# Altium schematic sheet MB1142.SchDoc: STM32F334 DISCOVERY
size A4; CompanyName: STM; DocumentNumber: MB1142; Revision: B-02; SheetNumber: 1; SheetTotal: 5; PageSetup: Record=PageOptions|CenterHorizontal=True|CenterVertical=True|PrintScale=-0.03|XCorrection=1.00|YCorrection=1.00|PrintKind=0|BorderSize=5000000|LeftOffset=0|BottomOffset=0|Orientation=2|PaperLength=1000|PaperWidth=1000|Scale=100|PaperSource=15|PrintQuality=1200|MediaType=1|DitherType=10|PaperKind=A4|PrintScaleMode=1; Project: STM32F3348-DISCO
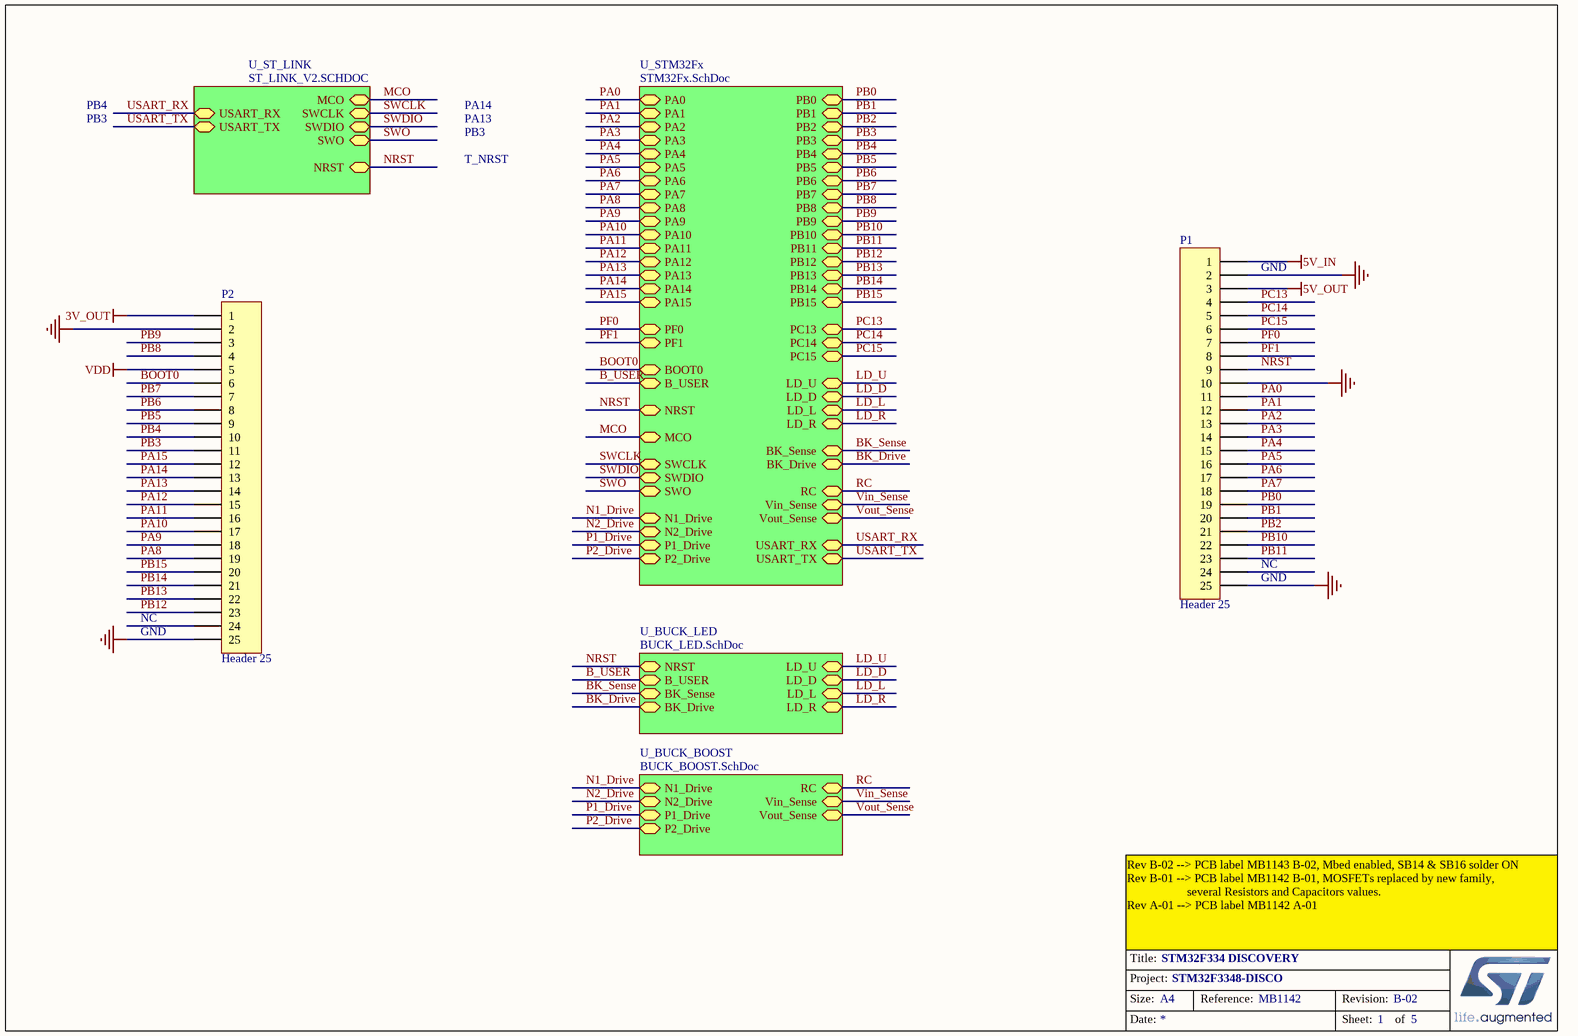
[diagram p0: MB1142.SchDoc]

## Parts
P1  Header 25  [HDR1X25]
P2  Header 25  [HDR1X25]

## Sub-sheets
U_BUCK_BOOST = BUCK_BOOST.SchDoc: N1_Drive, N2_Drive, Vout_Sense, P1_Drive, P2_Drive, Vin_Sense, RC
U_BUCK_LED = BUCK_LED.SchDoc: NRST, B_USER, BK_Sense, BK_Drive, LD_D, LD_U, LD_L, LD_R
U_ST_LINK = ST_LINK_V2.SCHDOC: NRST, MCO, SWDIO, SWCLK, SWO, USART_RX, USART_TX
U_STM32Fx = STM32Fx.SchDoc: PB8, BOOT0, NRST, PC15, PC14, PF1, PF0, MCO, PC13, PA0, PA1, PA2, PA3, PA4, PA5, PA6, PA7, PA8, PA9, PA10, PA11, PA12, PA13, PA14, PA15, PB0, PB1, PB2, PB3, PB4, PB5, PB6, PB7, PB9, PB10, PB11, PB12, PB13, PB14, PB15, B_USER, LD_D, LD_U, LD_L, LD_R, RC, Vout_Sense, P2_Drive, BK_Sense, Vin_Sense, BK_Drive, N1_Drive, P1_Drive, N2_Drive, SWCLK, SWDIO, SWO, USART_TX, USART_RX

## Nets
3V_OUT: P2.1
5V_IN: P1.1
5V_OUT: P1.3
GND: P1.2 P1.10 P1.25 P2.2 P2.25
VDD: P2.5
B_USER: sheet U_STM32Fx/B_USER, sheet U_BUCK_LED/B_USER
BK_Drive: sheet U_STM32Fx/BK_Drive, sheet U_BUCK_LED/BK_Drive
BK_Sense: sheet U_STM32Fx/BK_Sense, sheet U_BUCK_LED/BK_Sense
BOOT0: P2.6 ; sheet U_STM32Fx/BOOT0
LD_D: sheet U_STM32Fx/LD_D, sheet U_BUCK_LED/LD_D
LD_L: sheet U_STM32Fx/LD_L, sheet U_BUCK_LED/LD_L
LD_R: sheet U_STM32Fx/LD_R, sheet U_BUCK_LED/LD_R
LD_U: sheet U_STM32Fx/LD_U, sheet U_BUCK_LED/LD_U
MCO: sheet U_ST_LINK/MCO, sheet U_STM32Fx/MCO
N1_Drive: sheet U_STM32Fx/N1_Drive, sheet U_BUCK_BOOST/N1_Drive
N2_Drive: sheet U_STM32Fx/N2_Drive, sheet U_BUCK_BOOST/N2_Drive
NRST: P1.9 ; sheet U_ST_LINK/NRST, sheet U_STM32Fx/NRST, sheet U_BUCK_LED/NRST
P1_Drive: sheet U_STM32Fx/P1_Drive, sheet U_BUCK_BOOST/P1_Drive
P2_Drive: sheet U_STM32Fx/P2_Drive, sheet U_BUCK_BOOST/P2_Drive
PA0: P1.11 ; sheet U_STM32Fx/PA0
PA1: P1.12 ; sheet U_STM32Fx/PA1
PA2: P1.13 ; sheet U_STM32Fx/PA2
PA3: P1.14 ; sheet U_STM32Fx/PA3
PA4: P1.15 ; sheet U_STM32Fx/PA4
PA5: P1.16 ; sheet U_STM32Fx/PA5
PA6: P1.17 ; sheet U_STM32Fx/PA6
PA7: P1.18 ; sheet U_STM32Fx/PA7
PA8: P2.19 ; sheet U_STM32Fx/PA8
PA9: P2.18 ; sheet U_STM32Fx/PA9
PA10: P2.17 ; sheet U_STM32Fx/PA10
PA11: P2.16 ; sheet U_STM32Fx/PA11
PA12: P2.15 ; sheet U_STM32Fx/PA12
PA13: P2.14 ; sheet U_STM32Fx/PA13
PA14: P2.13 ; sheet U_STM32Fx/PA14
PA15: P2.12 ; sheet U_STM32Fx/PA15
PB0: P1.19 ; sheet U_STM32Fx/PB0
PB1: P1.20 ; sheet U_STM32Fx/PB1
PB2: P1.21 ; sheet U_STM32Fx/PB2
PB3: P2.11 ; sheet U_STM32Fx/PB3
PB4: P2.10 ; sheet U_STM32Fx/PB4
PB5: P2.9 ; sheet U_STM32Fx/PB5
PB6: P2.8 ; sheet U_STM32Fx/PB6
PB7: P2.7 ; sheet U_STM32Fx/PB7
PB8: P2.4 ; sheet U_STM32Fx/PB8
PB9: P2.3 ; sheet U_STM32Fx/PB9
PB10: P1.22 ; sheet U_STM32Fx/PB10
PB11: P1.23 ; sheet U_STM32Fx/PB11
PB12: P2.23 ; sheet U_STM32Fx/PB12
PB13: P2.22 ; sheet U_STM32Fx/PB13
PB14: P2.21 ; sheet U_STM32Fx/PB14
PB15: P2.20 ; sheet U_STM32Fx/PB15
PC13: P1.4 ; sheet U_STM32Fx/PC13
PC14: P1.5 ; sheet U_STM32Fx/PC14
PC15: P1.6 ; sheet U_STM32Fx/PC15
PF0: P1.7 ; sheet U_STM32Fx/PF0
PF1: P1.8 ; sheet U_STM32Fx/PF1
RC: sheet U_STM32Fx/RC, sheet U_BUCK_BOOST/RC
SWCLK: sheet U_ST_LINK/SWCLK, sheet U_STM32Fx/SWCLK
SWDIO: sheet U_ST_LINK/SWDIO, sheet U_STM32Fx/SWDIO
SWO: sheet U_ST_LINK/SWO, sheet U_STM32Fx/SWO
USART_RX: sheet U_ST_LINK/USART_RX, sheet U_STM32Fx/USART_RX
USART_TX: sheet U_ST_LINK/USART_TX, sheet U_STM32Fx/USART_TX
Vin_Sense: sheet U_STM32Fx/Vin_Sense, sheet U_BUCK_BOOST/Vin_Sense
Vout_Sense: sheet U_STM32Fx/Vout_Sense, sheet U_BUCK_BOOST/Vout_Sense

Not connected (* = marked no-connect by the designer): P1 24; P2 24

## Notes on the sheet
- PB4
- PA14
- PB3
- PA13
- T_NRST
- (near P1) GND
- (near P1) NC
- GND
- NC
- Rev B-02 --> PCB label MB1143 B-02, Mbed enabled, SB14 & SB16 solder ON
  Rev B-01 --> PCB label MB1142 B-01, MOSFETs replaced by new family,
  several Resistors and Capacitors values.
  Rev A-01 --> PCB label MB1142 A-01

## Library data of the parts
P1 P2 = Header 25: Header, 25-Pin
